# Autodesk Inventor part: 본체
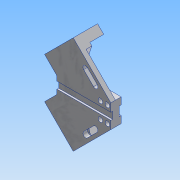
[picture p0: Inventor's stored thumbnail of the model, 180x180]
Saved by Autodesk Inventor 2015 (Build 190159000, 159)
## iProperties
Created: 2019-04
Part Number: 본체
Material: 알루미늄 6061
Document SubType Name: Modeling
Designer: user
Density: 2.7 g/cm^3
Appearance: 알루미늄 - 평지
Mass: 601.509 g
Surface Area: 426.536 cm^2
Volume: 222.781 cm^3
Author: user
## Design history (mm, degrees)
sketch "스케치1"
  geometry: L1 (-46.5, 20)-(46.5, 20); L2 (46.5, 20)-(46.5, -20); L3 (46.5, -20)-(-46.5, -20); L4 (-46.5, -20)-(-46.5, 20); L5 (-46.5, 20)-(46.5, -20); L6 (46.5, 20)-(-46.5, -20); 1 further point
  constraints: 12 end point, 2 midpoint, 2 parallel, 1 horizontal, 1 perpendicular
  dimensions: "d1" = 93 distance of L2.end L3.end; "d2" = 40 distance of L1.end L2.end
extrude "돌출1" new body sketch "스케치1" distance "d3" = 18; taper "d4" = 0 deg
sketch "스케치4"
  geometry: L1 (-46.5, 20)-(-46.5, -20) reference; L2 (-46.5, -8)-(46.5, -8); L3 (46.5, -8)-(46.5, 8); L4 (46.5, 8)-(-46.5, 8); L5 (-46.5, 8)-(-46.5, -8); L6 (46.5, -20)-(46.5, 20) reference; 4 further points
  constraints: 8 end point, 2 midpoint, 2 parallel, 1 horizontal, 1 perpendicular, 1 point on line
  dimensions: "d21" = 16 distance of L2.end L3.end
extrude "돌출4" cut sketch "스케치4" distance "d22" = 3.5; taper "d23" = 0 deg
sketch "스케치5"
  geometry: L1 (-46.5, 20)-(-46.5, -20) reference; L2 (-46.5, -6)-(46.5, -6); L3 (46.5, -6)-(46.5, 6); L4 (46.5, 6)-(-46.5, 6); L5 (-46.5, 6)-(-46.5, -6); L6 (46.5, -20)-(46.5, 20) reference; 6 further points
  constraints: 8 end point, 3 midpoint, 2 horizontal alignment, 2 parallel, 1 horizontal, 1 perpendicular, 1 point on line
  dimensions: "d24" = 12 distance of L2.end L3.end
extrude "돌출5" cut sketch "스케치5" distance "d25" = 3; taper "d26" = 0 deg
sketch "스케치8"
  geometry: L1 (46.5, -20)-(46.5, -6) reference; 3 further points
  dimensions: "d39" = 6 distance from line of L1 point (40.5, -14); "d40" = 14 vertical distance of point (0, 0) point (40.5, -14); "d41" = 12 distance of point (40.5, -14) point (28.5, -14); "d42" = 14 vertical distance of point (0, 0) point (28.5, -14)
hole "구멍1" sketch "스케치8" at (40.5, -14), (28.5, -14) diameter "d43" = 4.5; stored, may be unused: countersink angle "d47" = 90 deg, drill point angle "d49" = 118 deg; dims "d44" = 6, "d45" = 8, "d46" = 10, "d48" = 8
sketch "스케치10"
  geometry: L1 (-46.5, -8)-(-46.5, 8) reference; L2 (-46.5, 0)-(-66.5, 0); L3 (-46.5, -20)-(18.353, -84.853); L4 (18.353, -84.853)-(67.85, -35.355); L5 (67.85, -35.355)-(46.5, -14.005); L6 (46.5, -20)-(46.5, -8) reference; L7 (-46.5, -20)-(46.5, -20) reference; L8 (46.5, -14.005)-(46.5, -20); L9 (46.5, -20)-(-46.5, -20); L10 (46.5, -14.005)-(46.5, -20); L11 (46.5, -20)-(-46.5, -20); 1 further point
  constraints: 16 end point, 2 point on line, 2 vertical, 1 collinear, 1 horizontal, 1 midpoint, 1 perpendicular
  dimensions: "d62" = 20 distance of L2.start L2.end; "d63" = 120 distance of L2.end L3.end; "d64" = 45 deg angle of L2 L3; "d65" = 70 distance of L3.end L4.end; "d66" = 90 deg angle of L3 L4; "d67" = 91.71573 distance of L3.start L3.end; "d68" = 30.19387 distance of L4.end L5.end
extrude "돌출8" join sketch "스케치10" distance "d69" = 18; taper "d70" = 0 deg
sketch "스케치11"
  geometry: L1 (46.5, 20)-(-18.353, 84.853) reference; L2 (-18.353, 84.853)-(-67.85, 35.355) reference; L3 (-67.85, 35.355)-(-46.5, 14.005) reference; L4 (-57.244, 24.749)-(-7.746, 74.246); L5 (-57.244, 24.749)-(-67.85, 35.355); L6 (-67.85, 35.355)-(-18.353, 84.853); L7 (-18.353, 84.853)-(-7.746, 74.246); 1 further point
  constraints: 8 end point, 2 perpendicular, 2 point on line, 1 collinear
  dimensions: "d71" = 15 distance between parallel lines of L2 L4
extrude "돌출9" join sketch "스케치11" distance "d72" = 24; taper "d73" = 0 deg
sketch "스케치12"
  geometry: L1 (46.5, -20)-(-7.746, -74.246) reference; L2 (-4.211, -70.711)-(-11.282, -49.497); L3 (-11.282, -49.497)-(18.216, -20); L4 (18.216, -20)-(46.5, -20); L5 (-18.353, -84.853)-(-67.85, -35.355) reference; L6 (-11.282, -49.497)-(2.86, -63.64); L7 (-4.211, -70.711)-(46.5, -20); 1 further point
  constraints: 10 end point, 2 point on line, 1 horizontal, 1 parallel, 1 perpendicular
  dimensions: "d74" = 20 distance from line of L5 L2.start; "d75" = 30 distance of L5.start L6.end; "d76" = 20 distance of L6.end L2.end
extrude "돌출10" cut sketch "스케치12" distance "d77" = 10; taper "d78" = 0 deg
sketch "스케치13"
  geometry: L1 (46.5, -20)-(-4.211, -70.711) reference; L2 (2.86, -49.497)-(19.831, -32.527); L3 (-7.746, -74.246)-(-18.353, -84.853) reference; L4 (2.86, -49.497)-(9.931, -56.569); L5 (2.86, -49.497)-(19.831, -32.527); L6 (6.042, -52.679)-(23.013, -35.709); L7 (16.649, -29.345)-(-0.322, -46.315); A1 r 4.5 centre (2.86, -49.497) between (-0.322, -46.315) and (6.042, -52.679); A2 r 4.5 centre (19.831, -32.527) between (23.013, -35.709) and (16.649, -29.345); 2 further points
  constraints: 12 end point, 4 point on circle, 4 tangent, 2 centre point, 2 parallel, 1 collinear, 1 midpoint, 1 perpendicular, 1 point on line
  dimensions: "d79" = 10 distance from line of L3 L2.start; "d80" = 40 distance of L3.end L4.end; "d82" = 24 distance of L2.start L2.end; "d83" = 9 diameter of A2
extrude "돌출11" cut sketch "스케치13" distance "d84" = 10; taper "d85" = 0 deg
fillet "모깎기3" dims "d86" = 5
fillet "모깎기4" dims "d87" = 5
sketch "스케치14"
  geometry: L1 (0, 0)-(0, 70) reference; L2 (0, 70)-(15, 70) reference; 2 further points
  constraints: 1 other
  dimensions: "d88" = 7.5 distance from line of L1 point (7.5, 35); "d89" = 35 distance from line of L2 point (7.5, 35)
feature "엠보싱2" sketch "스케치14" dims "d1" = 93, "d2" = 40, "d90" = 0.5, "d91" = 0
node "솔리드1"
mirror "대칭5"
mirror "대칭6"
mirror "대칭7"
mirror "대칭8"
